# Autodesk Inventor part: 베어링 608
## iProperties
IsCustomPart: 1
Created: 2009-02
Part Number: 베어링 608
Material: 강, 연강
Description: 깊은 그루브 볼 베어링
Document SubType Name: Modeling
Standard: KS B 2023
Designer: 한국산업디자인학원
Standards Organization: KS
Language: ko-KR
Size Designation: 608 - 8 x 22 x 7
Categories: <MemberInstance><Categories><Category DisplayName="샤프트 부품" InternalName="7f7aeb1f-a693-4053-b835-cee3144e0d98" Mnemonic="SHFT"><Category DisplayName="베어링" Inter
Density: 1 g/cm^3
Author: 한국산업디자인학원
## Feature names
1. IDS_ARRAYBALL[SIMPL:T] [Circular Pattern]
